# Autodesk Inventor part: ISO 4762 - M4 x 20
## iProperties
Comments: To add or edit properties for Autodesk Inventor files, use iProperties.
Created: 2004-08
Part Number: ISO 4762 - M4 x 20
Vendor: Autodesk Inc.
Document SubType Name: Modeling
Designer: John Blackburn
Material: Default
Description: Hexagon Socket Head Cap Screw
Standard: ISO 4762
Alert: To add or edit properties for Autodesk Inventor files, use iProperties.
Control State: 0
Master: False
Checked Out: False
Shininess: 64.0
Length Units: 11269
Angle Units: 11279
Time Units: 11290
Mass Units: 11283
Length Display Precision: 3
Angle Display Precision: 2
Compacted: True
EGR: 1
Density: 0.0
Volumn: 0.0
Area: 0.0
PropertySet Name: Model Information
Author: John Blackburn
Revision Number: 8
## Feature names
1. Body [Revolution]
2. Slot [Extrusion]
3. Fillet1
4. Chamfer1
